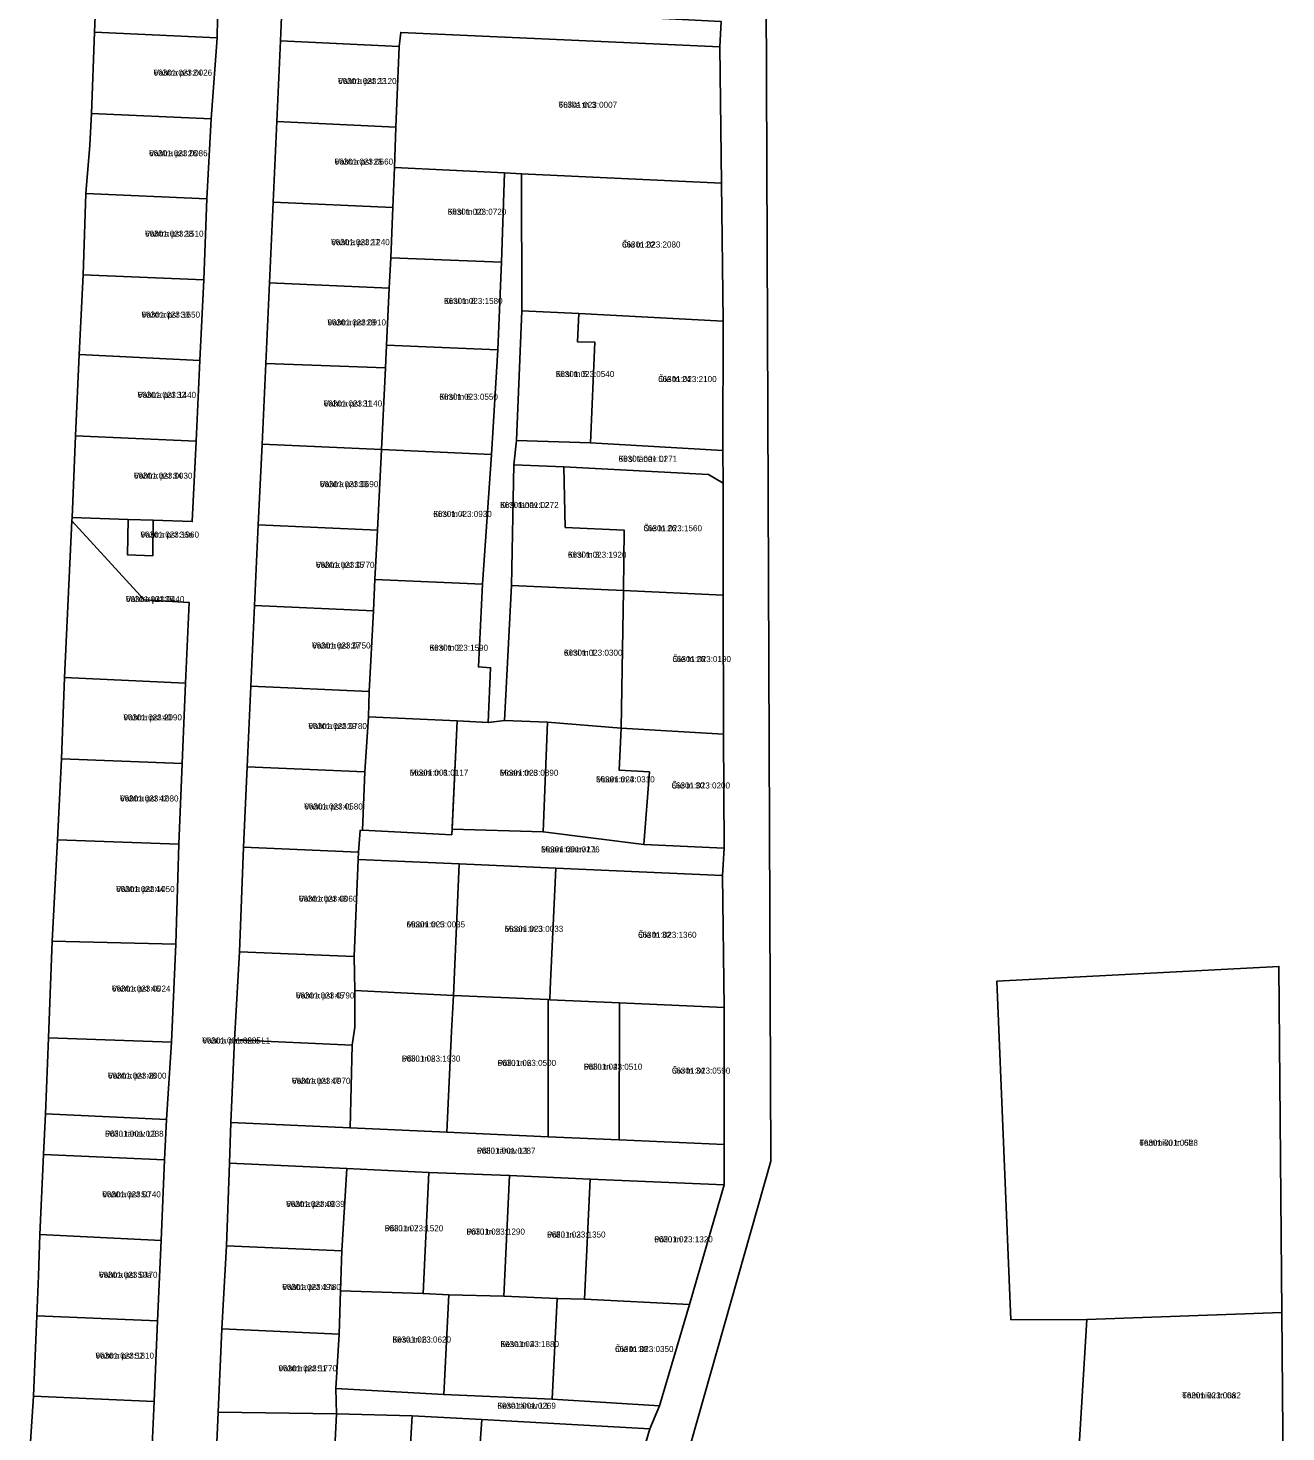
# Model space of a CAD drawing. Extents: x 632278 to 636344, y 6578401 to 6583362.
# Drawn here: x 633469.3 to 633781, y 6579911.1 to 6580259.1 of the extents above; entities that cross this region are included whole.
import ezdxf

# ---------------------------------------------------------------- set-up
doc = ezdxf.new("R2010")
doc.units = 0
for name, color, linetype in [('L_AADRESS', 7, 'Continuous'), ('PIIR', 7, 'Continuous'), ('TUNNUS', 7, 'Continuous')]:
    doc.layers.add(name, color=color, linetype=linetype)

msp = doc.modelspace()

# ---------------------------------------------------------------- linework, layer by layer
at = {"layer": 'PIIR'}
for points in [[(633605.51, 6579809.61), (633653.33, 6579978.24), (633651.84, 6580349.33), (633626.29, 6580542.71), (633673.01, 6580549.14), (633700.61, 6580504.19), (633703.74, 6580499.02), (633730.56, 6580496.56), (633754.85, 6580494.35), (633873.24, 6580487.78), (633957.63, 6580253.07), (633845.55, 6580021.57), (633842.59, 6580023.82), (633825.34, 6579983.05), (633800.65, 6579928), (633788.44, 6579901.57)], [(633626.29, 6580542.71), (633651.84, 6580349.33), (633653.33, 6579978.24), (633605.51, 6579809.61)], [(633499.6, 6579898.65), (633500.49, 6579918.63), (633501.36, 6579938.61), (633502.24, 6579958.59), (633503.12, 6579978.57), (633503.56, 6579988.53), (633504.8, 6580007.74), (633505.87, 6580031.97), (633506.63, 6580056.81), (633507.5, 6580076.79), (633508.3, 6580096.68), (633509.18, 6580116.71), (633498.01, 6580117.33), (633480.13, 6580136.89), (633480.17, 6580137.72), (633494.08, 6580137.26), (633493.95, 6580128.49), (633500.18, 6580128.28), (633500.31, 6580137.06), (633509.97, 6580136.75), (633510.9, 6580156.68), (633511.88, 6580176.65), (633512.87, 6580196.63), (633513.58, 6580216.69), (633514.67, 6580236.53), (633516.13, 6580256.6), (633516.28, 6580266.34)], [(633532.26, 6580265.84), (633531.82, 6580255.85), (633530.91, 6580235.87), (633529.99, 6580215.88), (633529.08, 6580195.89), (633528.16, 6580175.9), (633527.25, 6580155.91), (633526.33, 6580135.92), (633525.42, 6580115.93), (633524.5, 6580095.94), (633523.59, 6580075.95), (633522.68, 6580056.07), (633521.65, 6580030.09), (633520.44, 6580008.33), (633519.54, 6579987.8), (633519.18, 6579977.76), (633518.45, 6579957.27), (633517.29, 6579936.65), (633516.38, 6579916.02), (633515.47, 6579895.29)], [(633619.07, 6579897.15), (633623.38, 6579911.87), (633625.76, 6579917.61), (633633.2, 6579942.7), (633641.75, 6579972.34), (633641.77, 6579982.35), (633641.79, 6580016.34), (633641.38, 6580048.99), (633641.74, 6580055.79), (633641.64, 6580084.04), (633641.49, 6580118.47), (633641.54, 6580146.23), (633641.48, 6580154.35), (633641.52, 6580186.38), (633641.09, 6580220.6), (633640.7, 6580254.39), (633641.05, 6580260.68)], [(633780.33, 6579901.25), (633779.95, 6579940.68), (633779.23, 6580026.5), (633709.34, 6580022.83), (633712.84, 6579938.92), (633731.62, 6579938.95), (633729.12, 6579898.18)]]:
    msp.add_lwpolyline(points, dxfattribs=at)
for points in [[(633486.15, 6580268.01), (633516.28, 6580266.34), (633516.13, 6580256.6), (633485.7, 6580258.01)], [(633532.26, 6580265.84), (633561.66, 6580264.42), (633598.82, 6580262.77), (633620.05, 6580261.78), (633641.05, 6580260.68), (633640.7, 6580254.39), (633561.62, 6580257.97), (633561.25, 6580254.46), (633531.82, 6580255.85)], [(633485, 6580237.89), (633485.7, 6580258.01), (633516.13, 6580256.6), (633514.67, 6580236.53)], [(633561.62, 6580257.97), (633640.7, 6580254.39), (633641.1, 6580220.6), (633591.59, 6580222.94), (633587.32, 6580223.14), (633560.04, 6580224.53), (633560.4, 6580234.48), (633561.25, 6580254.46)], [(633531.82, 6580255.85), (633561.25, 6580254.46), (633560.4, 6580234.48), (633530.91, 6580235.87)], [(633514.67, 6580236.53), (633513.58, 6580216.69), (633483.58, 6580218.08), (633484.6, 6580230.06), (633485, 6580237.89)], [(633530.91, 6580235.87), (633560.4, 6580234.48), (633560.04, 6580224.53), (633559.65, 6580214.55), (633529.99, 6580215.88)], [(633587.32, 6580223.14), (633586.57, 6580201.02), (633559.16, 6580202.09), (633559.65, 6580214.55), (633560.04, 6580224.53)], [(633587.32, 6580223.14), (633591.59, 6580222.94), (633591.6, 6580189), (633590.34, 6580156.87), (633589.65, 6580150.84), (633589.1, 6580120.92), (633587.31, 6580087.46), (633583.28, 6580086.98), (633583.88, 6580100.53), (633580.89, 6580100.73), (633581.85, 6580121.19), (633584.12, 6580153.39), (633585.7, 6580179.27), (633586.57, 6580201.02)], [(633591.6, 6580189), (633591.59, 6580222.94), (633641.1, 6580220.6), (633641.52, 6580186.38), (633605.74, 6580188.29)], [(633482.92, 6580197.93), (633483.13, 6580202.96), (633483.58, 6580218.08), (633513.58, 6580216.69), (633512.87, 6580196.63)], [(633529.99, 6580215.88), (633559.65, 6580214.55), (633559.16, 6580202.09), (633558.73, 6580194.61), (633529.08, 6580195.89)], [(633558.73, 6580194.61), (633559.16, 6580202.09), (633586.57, 6580201.02), (633585.7, 6580179.27), (633558.13, 6580180.44)], [(633482.92, 6580197.93), (633512.87, 6580196.63), (633511.88, 6580176.65), (633481.91, 6580178.12)], [(633529.08, 6580195.89), (633558.73, 6580194.61), (633558.13, 6580180.44), (633557.85, 6580174.81), (633528.16, 6580175.9)], [(633590.34, 6580156.87), (633591.6, 6580189), (633605.74, 6580188.29), (633605.4, 6580181.29), (633609.74, 6580181.2), (633608.62, 6580156.24)], [(633609.74, 6580181.2), (633605.4, 6580181.29), (633605.74, 6580188.29), (633641.52, 6580186.38), (633641.48, 6580154.35), (633608.62, 6580156.24)], [(633481.91, 6580178.12), (633511.88, 6580176.65), (633510.9, 6580156.68), (633480.99, 6580157.98)], [(633557.85, 6580174.81), (633558.13, 6580180.44), (633585.7, 6580179.27), (633584.12, 6580153.39), (633556.85, 6580154.63)], [(633528.16, 6580175.9), (633557.85, 6580174.81), (633556.85, 6580154.63), (633527.25, 6580155.91)], [(633510.9, 6580156.68), (633509.97, 6580136.75), (633500.31, 6580137.06), (633494.08, 6580137.26), (633480.17, 6580137.72), (633480.99, 6580157.98)], [(633590.34, 6580156.87), (633608.62, 6580156.24), (633641.48, 6580154.35), (633641.54, 6580146.23), (633637.86, 6580148.42), (633602, 6580150.33), (633589.65, 6580150.84)], [(633555.85, 6580134.62), (633526.33, 6580135.92), (633527.25, 6580155.91), (633556.85, 6580154.63)], [(633555.85, 6580134.62), (633556.85, 6580154.63), (633584.12, 6580153.39), (633581.85, 6580121.19), (633555.24, 6580122.4)], [(633589.65, 6580150.84), (633602, 6580150.33), (633602.39, 6580135.29), (633617, 6580134.61), (633616.81, 6580119.66), (633589.1, 6580120.92)], [(633617, 6580134.61), (633602.39, 6580135.29), (633602, 6580150.33), (633637.86, 6580148.42), (633641.54, 6580146.23), (633641.49, 6580118.47), (633616.81, 6580119.66)], [(633498.01, 6580117.33), (633509.18, 6580116.71), (633508.3, 6580096.68), (633478.27, 6580098.12), (633480.13, 6580136.89)], [(633494.08, 6580137.26), (633500.31, 6580137.06), (633500.18, 6580128.28), (633493.95, 6580128.49)], [(633526.33, 6580135.92), (633555.85, 6580134.62), (633555.24, 6580122.4), (633554.84, 6580114.62), (633525.42, 6580115.93)], [(633553.84, 6580094.63), (633554.84, 6580114.62), (633555.24, 6580122.4), (633581.85, 6580121.19), (633580.89, 6580100.73), (633583.88, 6580100.53), (633583.28, 6580086.98), (633575.6, 6580087.34), (633553.66, 6580088.36)], [(633616.25, 6580085.51), (633598.03, 6580087), (633587.31, 6580087.46), (633589.1, 6580120.92), (633616.81, 6580119.66)], [(633616.81, 6580119.66), (633641.49, 6580118.47), (633641.64, 6580084.04), (633616.25, 6580085.51)], [(633553.84, 6580094.63), (633524.5, 6580095.94), (633525.42, 6580115.93), (633554.84, 6580114.62)], [(633478.27, 6580098.12), (633508.3, 6580096.68), (633507.5, 6580076.79), (633477.53, 6580077.93)], [(633524.5, 6580095.94), (633553.84, 6580094.63), (633553.66, 6580088.36), (633552.74, 6580074.7), (633523.59, 6580075.95)], [(633552.74, 6580074.7), (633553.66, 6580088.36), (633575.6, 6580087.34), (633574.36, 6580060.91), (633574.27, 6580059.14), (633552.12, 6580060.26)], [(633575.6, 6580087.34), (633583.35, 6580086.98), (633587.31, 6580087.46), (633598.03, 6580087), (633596.88, 6580059.86), (633574.33, 6580060.48)], [(633598.03, 6580087), (633616.25, 6580085.51), (633615.72, 6580075.17), (633623.23, 6580074.7), (633621.83, 6580056.72), (633596.88, 6580059.86)], [(633623.23, 6580074.7), (633615.72, 6580075.17), (633616.25, 6580085.51), (633641.64, 6580084.04), (633641.74, 6580055.79), (633621.83, 6580056.72)], [(633477.53, 6580077.93), (633507.5, 6580076.79), (633506.63, 6580056.81), (633476.59, 6580057.87)], [(633523.59, 6580075.95), (633552.74, 6580074.7), (633552.12, 6580060.26), (633551.54, 6580060.21), (633551.16, 6580054.82), (633522.68, 6580056.07)], [(633552.12, 6580060.26), (633574.27, 6580059.14), (633574.33, 6580060.48), (633596.88, 6580059.86), (633621.83, 6580056.72), (633641.74, 6580055.79), (633641.38, 6580048.99), (633600.09, 6580050.82), (633576.09, 6580051.88), (633551.07, 6580052.99), (633551.16, 6580054.82), (633551.54, 6580060.21)], [(633506.63, 6580056.81), (633505.87, 6580031.97), (633475.28, 6580032.76), (633476.59, 6580057.87)], [(633551.16, 6580054.82), (633551.07, 6580052.99), (633550.05, 6580028.96), (633521.65, 6580030.09), (633522.68, 6580056.07)], [(633550.28, 6580020.49), (633550.05, 6580028.96), (633551.07, 6580052.99), (633576.09, 6580051.88), (633574.68, 6580019.31)], [(633576.09, 6580051.88), (633600.09, 6580050.82), (633598.69, 6580020.84), (633598.59, 6580018.24), (633598.18, 6580018.27), (633574.68, 6580019.31)], [(633641.38, 6580048.99), (633641.79, 6580016.34), (633615.82, 6580017.49), (633598.59, 6580018.24), (633598.69, 6580020.84), (633600.09, 6580050.82)], [(633475.28, 6580032.76), (633505.87, 6580031.97), (633504.8, 6580007.74), (633474.3, 6580008.78)], [(633521.65, 6580030.09), (633550.05, 6580028.96), (633550.28, 6580020.49), (633550.27, 6580011.42), (633549.59, 6580006.99), (633520.44, 6580008.33)], [(633779.95, 6579940.68), (633731.62, 6579938.95), (633712.84, 6579938.92), (633709.34, 6580022.83), (633779.23, 6580026.5)], [(633549.59, 6580006.99), (633550.27, 6580011.42), (633550.28, 6580020.49), (633574.68, 6580019.31), (633574.24, 6580010.36), (633573.06, 6579985.39), (633549.09, 6579986.45)], [(633573.06, 6579985.39), (633574.24, 6580010.36), (633574.68, 6580019.31), (633598.18, 6580018.27), (633598.14, 6579984.27)], [(633598.18, 6580018.27), (633598.59, 6580018.24), (633615.82, 6580017.49), (633615.79, 6579983.49), (633598.14, 6579984.27)], [(633615.82, 6580017.49), (633641.79, 6580016.34), (633641.77, 6579982.35), (633615.79, 6579983.49)], [(633474.3, 6580008.78), (633504.8, 6580007.74), (633503.56, 6579988.53), (633473.61, 6579989.98)], [(633520.44, 6580008.33), (633549.59, 6580006.99), (633549.09, 6579986.45), (633519.54, 6579987.8)], [(633473.61, 6579989.98), (633503.56, 6579988.53), (633503.12, 6579978.57), (633473.13, 6579979.91)], [(633519.54, 6579987.8), (633549.09, 6579986.45), (633573.06, 6579985.39), (633598.14, 6579984.27), (633615.79, 6579983.49), (633641.77, 6579982.35), (633641.75, 6579972.34), (633608.58, 6579973.79), (633588.6, 6579974.68), (633568.62, 6579975.44), (633548.26, 6579976.37), (633519.18, 6579977.76)], [(633473.13, 6579979.91), (633503.12, 6579978.57), (633502.24, 6579958.59), (633472.2, 6579960.01)], [(633518.45, 6579957.27), (633519.18, 6579977.76), (633548.26, 6579976.37), (633547, 6579955.99)], [(633547, 6579955.99), (633548.26, 6579976.37), (633568.62, 6579975.44), (633567.2, 6579945.43), (633546.7, 6579946.11)], [(633567.2, 6579945.43), (633568.62, 6579975.44), (633588.6, 6579974.68), (633587.18, 6579944.73), (633573.52, 6579945.07)], [(633588.6, 6579974.68), (633608.58, 6579973.79), (633607.15, 6579943.98), (633600.39, 6579944.21), (633587.18, 6579944.73)], [(633608.58, 6579973.79), (633641.75, 6579972.34), (633633.2, 6579942.7), (633607.15, 6579943.98)], [(633471.47, 6579939.93), (633471.88, 6579949.79), (633472.2, 6579960.01), (633502.24, 6579958.59), (633501.36, 6579938.61)], [(633518.45, 6579957.27), (633547, 6579955.99), (633546.7, 6579946.11), (633546.35, 6579935.34), (633517.29, 6579936.65)], [(633545.56, 6579921.84), (633546.35, 6579935.34), (633546.7, 6579946.11), (633567.2, 6579945.43), (633573.52, 6579945.07), (633572.31, 6579920.43)], [(633573.52, 6579945.07), (633587.18, 6579944.73), (633600.39, 6579944.21), (633599.17, 6579919.24), (633572.31, 6579920.43)], [(633625.76, 6579917.61), (633599.17, 6579919.24), (633600.39, 6579944.21), (633607.15, 6579943.98), (633633.2, 6579942.7)], [(633471.47, 6579939.93), (633501.36, 6579938.61), (633500.49, 6579918.63), (633470.59, 6579919.96)], [(633731.62, 6579938.95), (633779.95, 6579940.68), (633780.33, 6579901.25), (633729.12, 6579898.18)], [(633517.29, 6579936.65), (633546.35, 6579935.34), (633545.56, 6579921.84), (633545.72, 6579915.59), (633516.38, 6579916.02)], [(633545.56, 6579921.84), (633572.31, 6579920.43), (633599.17, 6579919.24), (633625.76, 6579917.61), (633623.38, 6579911.87), (633581.71, 6579914.22), (633564.48, 6579915.08), (633545.72, 6579915.59)], [(633500.49, 6579918.63), (633499.6, 6579898.65), (633469.28, 6579899.93), (633470.59, 6579919.96)], [(633516.38, 6579916.02), (633545.72, 6579915.59), (633544.66, 6579894.02), (633515.47, 6579895.29)], [(633544.66, 6579894.02), (633545.72, 6579915.59), (633564.48, 6579915.08), (633562.57, 6579882.95), (633544.14, 6579883.81)], [(633562.57, 6579882.95), (633564.48, 6579915.08), (633581.71, 6579914.22), (633580.62, 6579899.05), (633580, 6579882.41), (633566.37, 6579882.6)], [(633623.38, 6579911.87), (633619.07, 6579897.15), (633580.62, 6579899.05), (633581.71, 6579914.22)]]:
    msp.add_lwpolyline(points, close=True, dxfattribs=at)

# ---------------------------------------------------------------- texts
at = {"layer": 'L_AADRESS'}
for s, p in [('Vahtra pst 24', (633500.39, 6580247.27)), ('Vahtra pst 23', (633546.09, 6580245.17)), ('Tulika tn 3', (633600.74, 6580239.29)), ('Vahtra pst 26', (633499.26, 6580227.29)), ('Vahtra pst 25', (633545.24, 6580225.21)), ('Kirsi tn 10', (633573.27, 6580212.78)), ('Vahtra pst 28', (633498.26, 6580207.35)), ('Vahtra pst 27', (633544.39, 6580205.24)), ('Õie tn 22', (633616.45, 6580204.66)), ('Kirsi tn 8', (633572.36, 6580190.68)), ('Vahtra pst 30', (633497.39, 6580187.29)), ('Vahtra pst 29', (633543.47, 6580185.35)), ('Kirsi tn 5', (633600.04, 6580172.56)), ('Õie tn 24', (633625.4, 6580171.32)), ('Vahtra pst 32', (633496.42, 6580167.4)), ('Kirsi tn 6', (633571.2, 6580166.92)), ('Vahtra pst 31', (633542.53, 6580165.26)), ('Kirsi tänav L1', (633615.62, 6580151.55)), ('Vahtra pst 34', (633495.51, 6580147.37)), ('Vahtra pst 33', (633541.57, 6580145.27)), ('Kirsi tn 4', (633569.68, 6580137.89)), ('Kirsi tänav L2', (633586.25, 6580140.11)), ('Õie tn 26', (633621.77, 6580134.35)), ('Vahtra pst 36a', (633497.13, 6580132.77)), ('Kirsi tn 3', (633603.05, 6580127.77)), ('Vahtra pst 35', (633540.61, 6580125.27)), ('Vahtra pst 38', (633493.5, 6580116.79)), ('Vahtra pst 37', (633539.65, 6580105.28)), ('Kirsi tn 2', (633568.77, 6580104.72)), ('Kirsi tn 1', (633602.06, 6580103.5)), ('Õie tn 28', (633628.95, 6580101.92)), ('Vahtra pst 40', (633492.9, 6580087.46)), ('Vahtra pst 39', (633538.74, 6580085.32)), ('Mooni tn 8', (633563.86, 6580073.78)), ('Mooni tn 6', (633586.18, 6580073.74)), ('Mooni tn 4', (633610.05, 6580072.11)), ('Õie tn 30', (633628.73, 6580070.59)), ('Vahtra pst 42', (633492.06, 6580067.37)), ('Vahtra pst 41', (633537.72, 6580065.38)), ('Mooni tänav L1', (633596.42, 6580054.74)), ('Vahtra pst 44', (633491.09, 6580044.92)), ('Vahtra pst 43', (633536.38, 6580042.52)), ('Mooni tn 5', (633563.07, 6580036.16)), ('Mooni tn 3', (633587.39, 6580035.06)), ('Õie tn 32', (633620.43, 6580033.58)), ('Vahtra pst 46', (633490.06, 6580020.25)), ('Vahtra pst 45', (633535.64, 6580018.54)), ('Vahtra puiestee L1', (633512.45, 6580007.38)), ('Põllu tn 8', (633561.89, 6580002.91)), ('Põllu tn 6', (633585.62, 6580001.83)), ('Põllu tn 4', (633606.98, 6580000.88)), ('Õie tn 34', (633628.79, 6579999.92)), ('Vahtra pst 48', (633489.07, 6579998.66)), ('Vahtra pst 47', (633534.66, 6579997.39)), ('Põllu tänav L2', (633488.36, 6579984.28)), ('Tammiku tn 6b', (633744.65, 6579982.05)), ('Põllu tänav L1', (633580.51, 6579980.07)), ('Vahtra pst 50', (633487.67, 6579969.25)), ('Vahtra pst 49', (633533.23, 6579966.88)), ('Põllu tn 7', (633557.66, 6579960.84)), ('Põllu tn 5', (633577.9, 6579960.02)), ('Põllu tn 3', (633597.88, 6579959.29)), ('Põllu tn 1', (633624.45, 6579958.11)), ('Vahtra pst 50a', (633486.85, 6579949.31)), ('Vahtra pst 49a', (633532.27, 6579946.3)), ('Kesa tn 6', (633559.58, 6579933.27)), ('Vahtra pst 52', (633485.98, 6579929.28)), ('Kesa tn 4', (633586.34, 6579932.15)), ('Õie tn 38', (633614.72, 6579930.91)), ('Vahtra pst 51', (633531.32, 6579926.12)), ('Tammiku tn 6a', (633755.29, 6579919.43)), ('Kesa tänav L1', (633585.57, 6579916.86))]:
    msp.add_text(s, height=1.5, dxfattribs=at).set_placement(p)
at = {"layer": 'TUNNUS'}
for s, p in [('66301:023:0026', (633500.39, 6580247.27)), ('66301:023:1120', (633546.09, 6580245.17)), ('66301:023:0007', (633600.74, 6580239.29)), ('66301:023:0086', (633499.26, 6580227.29)), ('66301:023:0660', (633545.24, 6580225.21)), ('66301:023:0720', (633573.27, 6580212.78)), ('66301:023:1510', (633498.26, 6580207.35)), ('66301:023:1240', (633544.39, 6580205.24)), ('66301:023:2080', (633616.45, 6580204.66)), ('66301:023:1580', (633572.36, 6580190.68)), ('66301:023:1650', (633497.39, 6580187.29)), ('66301:023:0910', (633543.47, 6580185.35)), ('66301:023:0540', (633600.04, 6580172.56)), ('66301:023:2100', (633625.4, 6580171.32)), ('66301:023:1440', (633496.42, 6580167.4)), ('66301:023:0550', (633571.2, 6580166.92)), ('66301:023:1140', (633542.53, 6580165.26)), ('66301:001:0271', (633615.62, 6580151.55)), ('66301:023:0030', (633495.51, 6580147.37)), ('66301:023:0690', (633541.57, 6580145.27)), ('66301:001:0272', (633586.25, 6580140.11)), ('66301:023:0930', (633569.68, 6580137.89)), ('66301:023:1960', (633497.13, 6580132.77)), ('66301:023:1560', (633621.77, 6580134.35)), ('66301:023:1920', (633603.05, 6580127.77)), ('66301:023:0770', (633540.61, 6580125.27)), ('66301:023:0440', (633493.5, 6580116.79)), ('66301:023:0750', (633539.65, 6580105.28)), ('66301:023:1590', (633568.77, 6580104.72)), ('66301:023:0300', (633602.06, 6580103.5)), ('66301:023:0190', (633628.95, 6580101.92)), ('66301:023:2090', (633492.9, 6580087.46)), ('66301:023:0780', (633538.74, 6580085.32)), ('66301:001:0117', (633563.86, 6580073.78)), ('66301:023:0890', (633586.18, 6580073.74)), ('66301:023:0310', (633610.05, 6580072.11)), ('66301:023:0200', (633628.73, 6580070.59)), ('66301:023:1080', (633492.06, 6580067.37)), ('66301:023:0580', (633537.72, 6580065.38)), ('66301:001:0276', (633596.42, 6580054.74)), ('66301:023:1050', (633491.09, 6580044.92)), ('66301:023:0060', (633536.38, 6580042.52)), ('66301:023:0035', (633563.07, 6580036.16)), ('66301:023:0033', (633587.39, 6580035.06)), ('66301:023:1360', (633620.43, 6580033.58)), ('66301:023:0024', (633490.06, 6580020.25)), ('66301:023:0790', (633535.64, 6580018.54)), ('66301:001:0285', (633512.45, 6580007.38)), ('66301:023:1930', (633561.89, 6580002.91)), ('66301:023:0500', (633585.62, 6580001.83)), ('66301:023:0510', (633606.98, 6580000.88)), ('66301:023:0590', (633628.79, 6579999.92)), ('66301:023:2000', (633489.07, 6579998.66)), ('66301:023:0970', (633534.66, 6579997.39)), ('66301:001:0288', (633488.36, 6579984.28)), ('66301:001:0528', (633744.65, 6579982.05)), ('66301:001:0287', (633580.51, 6579980.07)), ('66301:023:0740', (633487.67, 6579969.25)), ('66301:023:0039', (633533.23, 6579966.88)), ('66301:023:1520', (633557.66, 6579960.84)), ('66301:023:1290', (633577.9, 6579960.02)), ('66301:023:1350', (633597.88, 6579959.29)), ('66301:023:1320', (633624.45, 6579958.11)), ('66301:023:0470', (633486.85, 6579949.31)), ('66301:023:1780', (633532.27, 6579946.3)), ('66301:023:0620', (633559.58, 6579933.27)), ('66301:023:1810', (633485.98, 6579929.28)), ('66301:023:1880', (633586.34, 6579932.15)), ('66301:023:0350', (633614.72, 6579930.91)), ('66301:023:1770', (633531.32, 6579926.12)), ('66301:023:0082', (633755.29, 6579919.43)), ('66301:001:0269', (633585.57, 6579916.86))]:
    msp.add_text(s, height=1.5, dxfattribs=at).set_placement(p)

doc.saveas('drawing.dxf')
